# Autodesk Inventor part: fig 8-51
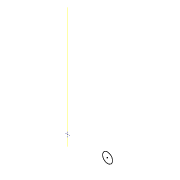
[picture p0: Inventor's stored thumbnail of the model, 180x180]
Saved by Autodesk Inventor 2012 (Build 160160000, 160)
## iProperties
Shininess: 77.0
Length Units: 11269
Angle Units: 11279
Time Units: 11290
Mass Units: 11283
Length Display Precision: 3
Angle Display Precision: 2
Created: 2002-01
Part Number: fig 8-51
Document SubType Name: Modeling
Designer: CADSoft
Density: 1 g/cm^3
Material: Default
Density: 0.0
Volumn: 0.0
Area: 0.0
PropertySet Name: Model Information
Control State: 0
Master: False
Checked Out: False
Author: CADSoft
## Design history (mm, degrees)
sketch "Sketch2"
  geometry: C1 r 2.5 at (-20, -0.092); 1 further point
  constraints: 1 centre point, 2 other
workaxis "Work Axis1"
body "Solid1"
